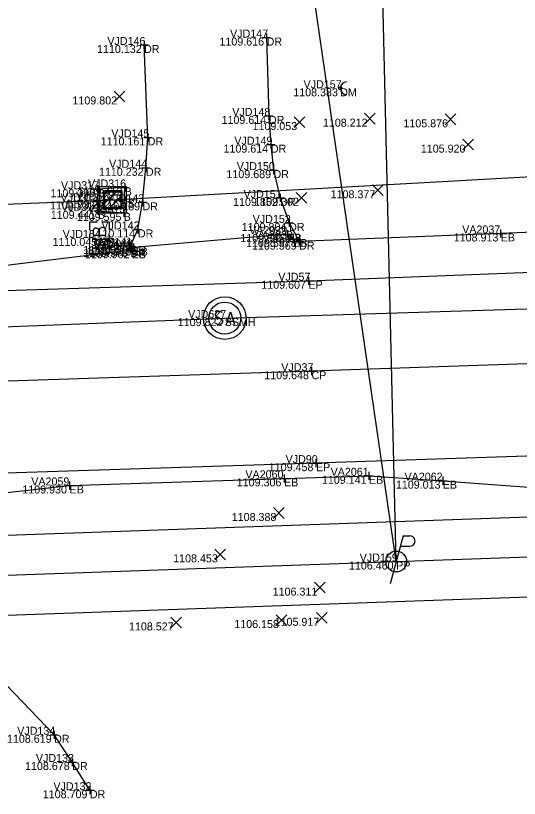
# Model space of a CAD drawing. Extents: x 1629915 to 1630675, y 484401 to 484601.
# Drawn here: x 1630022 to 1630085, y 484428.3 to 484526.1 of the extents above; entities that cross this region are included whole.
import ezdxf

# ---------------------------------------------------------------- set-up
doc = ezdxf.new("R2010")
doc.units = 0
for name, color, linetype in [('BR_X_Sub_Foot_Object', 7, 'Continuous'), ('DR_X_Cells', 7, 'Continuous'), ('DR_X_Storm_Sewer', 7, 'Continuous'), ('GK_Drainage_Nodes', 7, 'Continuous'), ('PV_X_COP', 7, 'Continuous'), ('PV_X_Driveway', 7, 'Continuous'), ('PV_X_EOP', 7, 'Continuous'), ('PV_X_Shoulder_Aggregate', 7, 'Continuous'), ('RD_X_Cells', 7, 'Continuous'), ('SV_X_Break_Lines', 7, 'Continuous'), ('SV_X_Random_Point', 7, 'Continuous'), ('SV_X_Shot_Marker', 7, 'Continuous'), ('SV_X_Text_Comment', 7, 'Continuous'), ('SV_X_Text_Elevation', 7, 'Continuous'), ('SV_X_Text_Name', 7, 'Continuous'), ('UT_X_Electric_Cells', 7, 'Continuous'), ('UT_X_Misc_Cells', 7, 'Continuous'), ('UT_X_Sanitary_Cells', 7, 'Continuous'), ('UT_X_Sanitary_Line', 7, 'Continuous')]:
    doc.layers.add(name, color=color, linetype=linetype)

msp = doc.modelspace()

# ---------------------------------------------------------------- linework, layer by layer
at = {"layer": 'BR_X_Sub_Foot_Object'}
for p, q in [((1630069.563, 484457.901), (1630057.616, 484540.101)), ((1630069.563, 484457.901), (1630067.613, 484539.935)), ((1629921.46, 484457.7), (1630334.806, 484472.223)), ((1629921.635, 484452.703), (1630334.981, 484467.226)), ((1629921.811, 484447.706), (1630335.157, 484462.229))]:
    msp.add_line(p, q, dxfattribs=at)
at = {"layer": 'DR_X_Cells'}
for p, q in [((1630032.993, 484502.475), (1630034.752, 484504.234)), ((1630032.993, 484503.607), (1630033.621, 484504.234)), ((1630033.592, 484501.943), (1630035.285, 484503.636)), ((1630034.723, 484501.943), (1630035.285, 484502.504))]:
    msp.add_line(p, q, dxfattribs=at)
for points in [[(1630032.472, 484504.755), (1630035.805, 484504.755), (1630035.805, 484501.422), (1630032.472, 484501.422)], [(1630032.993, 484504.234), (1630035.285, 484504.234), (1630035.285, 484501.943), (1630032.993, 484501.943)], [(1630033.139, 484504.088), (1630035.139, 484504.088), (1630035.139, 484502.088), (1630033.139, 484502.088)]]:
    msp.add_lwpolyline(points, close=True, dxfattribs=at)
at = {"layer": 'DR_X_Storm_Sewer'}
for p, q in [((1630034.139, 484503.088), (1630277.798, 484516.548)), ((1629929.219, 484498.911), (1630034.139, 484503.088))]:
    msp.add_line(p, q, dxfattribs=at)
at = {"layer": 'GK_Drainage_Nodes'}
for p, q in [((1630034.139, 484504.755), (1630034.139, 484504.755)), ((1630034.139, 484504.088), (1630034.139, 484504.088)), ((1630033.139, 484503.088), (1630033.139, 484503.088)), ((1630034.139, 484503.088), (1630034.139, 484503.088)), ((1630034.139, 484503.088), (1630034.139, 484503.088)), ((1630034.139, 484503.088), (1630034.139, 484503.088)), ((1630035.139, 484503.088), (1630035.139, 484503.088)), ((1630034.139, 484502.088), (1630034.139, 484502.088)), ((1630034.139, 484501.422), (1630034.139, 484501.422)), ((1630048.132, 484490.308), (1630048.132, 484490.308)), ((1630048.132, 484488.308), (1630048.132, 484488.308)), ((1630048.132, 484488.308), (1630048.132, 484488.308)), ((1630048.132, 484488.308), (1630048.132, 484488.308)), ((1630048.132, 484486.308), (1630048.132, 484486.308))]:
    msp.add_line(p, q, dxfattribs=at)
msp.add_circle((1630048.132, 484488.308), 2, dxfattribs=at)
at = {"layer": 'PV_X_COP'}
msp.add_lwpolyline([(1630268.327, 484489.246), (1630243.236, 484488.193), (1630219.614, 484487.396), (1630181.886, 484485.929), (1630141.907, 484484.591), (1630101.847, 484483.155), (1630058.972, 484481.674), (1630018.452, 484480.335), (1629978.036, 484478.791), (1629939.203, 484477.211)], dxfattribs=at)
at = {"layer": 'PV_X_Driveway'}
for points in [[(1630053.369, 484523.345), (1630053.65, 484513.559), (1630053.895, 484509.971), (1630054.225, 484506.785), (1630055.045, 484503.31), (1630056.173, 484500.192), (1630057.423, 484497.854)], [(1630036.34, 484496.941), (1630036.368, 484497.325), (1630037.277, 484499.378), (1630037.85, 484502.77), (1630038.279, 484507.079), (1630038.501, 484510.88), (1630038.044, 484522.417)], [(1630031.272, 484429.335), (1630029.073, 484432.859), (1630026.796, 484436.262), (1630014.842, 484448.677), (1630013.22, 484450.84), (1630012.363, 484454.308), (1630013.213, 484458.887), (1630014.53, 484461.746), (1630016.574, 484465.202)]]:
    msp.add_lwpolyline(points, dxfattribs=at)
at = {"layer": 'PV_X_EOP'}
for points in [[(1629938.787, 484488.624), (1629977.755, 484490.201), (1630018.109, 484491.66), (1630058.596, 484492.972), (1630101.458, 484494.639), (1630141.527, 484496.094), (1630181.4, 484497.615), (1630219.199, 484499.135), (1630242.799, 484500.003), (1630272.749, 484501.051)], [(1630263.784, 484477.407), (1630243.533, 484476.684), (1630220.003, 484475.815), (1630182.217, 484474.501), (1630142.357, 484473.071), (1630102.121, 484471.603), (1630059.531, 484470.186), (1630018.192, 484468.838), (1629978.308, 484467.435), (1629939.56, 484465.905)]]:
    msp.add_lwpolyline(points, dxfattribs=at)
at = {"layer": 'PV_X_Shoulder_Aggregate'}
for points in [[(1630275.858, 484507.82), (1630275.935, 484508.43), (1630251.773, 484507.981), (1630226.056, 484507.184), (1630204.993, 484506.289), (1630180.178, 484504.732), (1630155.752, 484502.786), (1630130.505, 484501.377), (1630107.341, 484499.869), (1630082.614, 484498.877), (1630057.423, 484497.854), (1630056.684, 484498.178), (1630055.974, 484498.791), (1630036.737, 484497.117), (1630036.516, 484496.78), (1630005.439, 484492.996), (1629981.146, 484491.329), (1629968.094, 484490.842), (1629967.166, 484490.748), (1629965.306, 484491.801), (1629947.85, 484491.524), (1629935.773, 484490.2), (1629921.037, 484489.433)], [(1629924.92, 484463.104), (1629930.051, 484463.83), (1629958.351, 484464.985), (1629985.484, 484465.939), (1629989.882, 484465.788), (1629994.282, 484464.53), (1629995.636, 484464.345), (1630011.361, 484464.736), (1630016.574, 484465.202), (1630018.985, 484466.333), (1630028.743, 484467.401), (1630055.537, 484468.29), (1630066.153, 484468.607), (1630075.383, 484468), (1630095.195, 484466.534), (1630119.644, 484467.176), (1630148.034, 484467.946), (1630167.26, 484468.813), (1630191.18, 484469.683), (1630216.422, 484470.188), (1630228.431, 484470.017), (1630254.625, 484470.782), (1630261.494, 484471.006)]]:
    msp.add_lwpolyline(points, dxfattribs=at)
at = {"layer": 'RD_X_Cells'}
for p, q in [((1630031.261, 484497.807), (1630031.261, 484498.808)), ((1630033.704, 484497.807), (1630033.704, 484498.808)), ((1630032.482, 484498.318), (1630032.482, 484498.318))]:
    msp.add_line(p, q, dxfattribs=at)
for points in [[(1630031.261, 484499.325), (1630031.261, 484500.318), (1630032.231, 484500.318)], [(1630032.734, 484500.318), (1630033.704, 484500.318), (1630033.704, 484499.325)], [(1630032.413, 484499.34), (1630032.35, 484499.403), (1630032.312, 484499.441), (1630032.275, 484499.466), (1630032.249, 484499.479), (1630032.199, 484499.504), (1630032.161, 484499.516), (1630032.073, 484499.542), (1630032.035, 484499.542), (1630031.985, 484499.542), (1630031.909, 484499.529), (1630031.846, 484499.504), (1630031.796, 484499.466), (1630031.745, 484499.403), (1630031.72, 484499.353), (1630031.708, 484499.327), (1630031.682, 484499.264), (1630031.682, 484498.647), (1630033.282, 484498.647), (1630033.282, 484499.34), (1630033.232, 484499.428), (1630033.169, 484499.504), (1630033.068, 484499.567), (1630032.955, 484499.605), (1630032.841, 484499.617), (1630032.766, 484499.617), (1630032.69, 484499.592), (1630032.577, 484499.542), (1630032.501, 484499.479), (1630032.413, 484499.34), (1630032.413, 484498.647)], [(1630033.282, 484497.022), (1630031.682, 484497.022), (1630033.282, 484497.601), (1630031.682, 484498.156), (1630033.282, 484498.156)], [(1630032.231, 484496.318), (1630031.261, 484496.318), (1630031.261, 484497.288)], [(1630033.704, 484497.288), (1630033.704, 484496.318), (1630032.734, 484496.318)]]:
    msp.add_lwpolyline(points, dxfattribs=at)
at = {"layer": 'SV_X_Break_Lines'}
msp.add_lwpolyline([(1630032.155, 484502.881), (1630032.273, 484501.704), (1630035.509, 484501.451), (1630035.629, 484504.618), (1630032.237, 484504.402)], dxfattribs=at)
at = {"layer": 'SV_X_Random_Point'}
for p, q in [((1630034.301, 484515.325), (1630035.635, 484516.66)), ((1630034.301, 484516.66), (1630035.635, 484515.325)), ((1630056.798, 484512.124), (1630058.131, 484513.459)), ((1630056.798, 484513.459), (1630058.131, 484512.124)), ((1630065.604, 484512.549), (1630066.937, 484513.884)), ((1630065.604, 484513.884), (1630066.937, 484512.549)), ((1630075.695, 484512.465), (1630077.029, 484513.8)), ((1630075.695, 484513.8), (1630077.029, 484512.465)), ((1630077.883, 484509.31), (1630079.216, 484510.645)), ((1630077.883, 484510.645), (1630079.216, 484509.31)), ((1630066.591, 484503.602), (1630067.925, 484504.937)), ((1630066.591, 484504.937), (1630067.925, 484503.602)), ((1630057.038, 484502.676), (1630058.372, 484504.011)), ((1630057.038, 484504.011), (1630058.372, 484502.676)), ((1630054.24, 484463.294), (1630055.573, 484464.629)), ((1630054.24, 484464.629), (1630055.573, 484463.294)), ((1630046.88, 484458.128), (1630048.213, 484459.463)), ((1630046.88, 484459.463), (1630048.213, 484458.128)), ((1630059.336, 484453.971), (1630060.669, 484455.306)), ((1630059.336, 484455.306), (1630060.669, 484453.971)), ((1630041.392, 484449.626), (1630042.725, 484450.961)), ((1630041.392, 484450.961), (1630042.725, 484449.626)), ((1630054.555, 484449.922), (1630055.888, 484451.257)), ((1630054.555, 484451.257), (1630055.888, 484449.922)), ((1630059.594, 484450.204), (1630060.927, 484451.539)), ((1630059.594, 484451.539), (1630060.927, 484450.204))]:
    msp.add_line(p, q, dxfattribs=at)
at = {"layer": 'SV_X_Shot_Marker'}
for p, q in [((1630052.869, 484523.345), (1630053.869, 484523.345)), ((1630053.369, 484523.845), (1630053.369, 484522.845)), ((1630053.369, 484523.345), (1630053.369, 484523.345)), ((1630037.544, 484522.417), (1630038.544, 484522.417)), ((1630038.044, 484522.917), (1630038.044, 484521.917)), ((1630038.044, 484522.417), (1630038.044, 484522.417)), ((1630053.15, 484513.559), (1630054.15, 484513.559)), ((1630053.65, 484514.059), (1630053.65, 484513.059)), ((1630053.65, 484513.559), (1630053.65, 484513.559)), ((1630038.001, 484510.88), (1630039.001, 484510.88)), ((1630038.501, 484511.38), (1630038.501, 484510.38)), ((1630038.501, 484510.88), (1630038.501, 484510.88)), ((1630053.895, 484510.471), (1630053.895, 484509.471)), ((1630053.395, 484509.971), (1630054.395, 484509.971)), ((1630053.895, 484509.971), (1630053.895, 484509.971)), ((1630038.279, 484507.579), (1630038.279, 484506.579)), ((1630037.779, 484507.079), (1630038.779, 484507.079)), ((1630038.279, 484507.079), (1630038.279, 484507.079)), ((1630053.725, 484506.785), (1630054.725, 484506.785)), ((1630054.225, 484507.285), (1630054.225, 484506.285)), ((1630054.225, 484506.785), (1630054.225, 484506.785)), ((1630032.237, 484504.902), (1630032.237, 484503.902)), ((1630035.129, 484504.618), (1630036.129, 484504.618)), ((1630035.629, 484505.118), (1630035.629, 484504.118)), ((1630035.629, 484504.618), (1630035.629, 484504.618)), ((1630031.737, 484504.402), (1630032.737, 484504.402)), ((1630032.237, 484504.402), (1630032.237, 484504.402)), ((1630055.045, 484503.81), (1630055.045, 484502.81)), ((1630031.655, 484502.881), (1630032.655, 484502.881)), ((1630032.155, 484503.381), (1630032.155, 484502.381)), ((1630032.155, 484502.881), (1630032.155, 484502.881)), ((1630037.35, 484502.77), (1630038.35, 484502.77)), ((1630037.85, 484503.27), (1630037.85, 484502.27)), ((1630037.85, 484502.77), (1630037.85, 484502.77)), ((1630054.545, 484503.31), (1630055.545, 484503.31)), ((1630055.045, 484503.31), (1630055.045, 484503.31)), ((1630031.773, 484501.704), (1630032.773, 484501.704)), ((1630032.273, 484502.204), (1630032.273, 484501.204)), ((1630032.273, 484501.704), (1630032.273, 484501.704)), ((1630035.509, 484501.951), (1630035.509, 484500.951)), ((1630035.009, 484501.451), (1630036.009, 484501.451)), ((1630035.509, 484501.451), (1630035.509, 484501.451)), ((1630056.173, 484500.692), (1630056.173, 484499.692)), ((1630037.277, 484499.878), (1630037.277, 484498.878)), ((1630055.673, 484500.192), (1630056.673, 484500.192)), ((1630056.173, 484500.192), (1630056.173, 484500.192)), ((1630036.777, 484499.378), (1630037.777, 484499.378)), ((1630037.277, 484499.378), (1630037.277, 484499.378)), ((1630055.474, 484498.791), (1630056.474, 484498.791)), ((1630055.974, 484499.291), (1630055.974, 484498.291)), ((1630055.974, 484498.791), (1630055.974, 484498.791)), ((1630082.114, 484498.877), (1630083.114, 484498.877)), ((1630082.614, 484499.377), (1630082.614, 484498.377)), ((1630082.614, 484498.877), (1630082.614, 484498.877)), ((1630036.368, 484497.825), (1630036.368, 484496.825)), ((1630056.184, 484498.178), (1630057.184, 484498.178)), ((1630056.684, 484498.678), (1630056.684, 484497.678)), ((1630056.684, 484498.178), (1630056.684, 484498.178)), ((1630056.923, 484497.854), (1630057.923, 484497.854)), ((1630057.423, 484498.354), (1630057.423, 484497.354)), ((1630057.423, 484497.854), (1630057.423, 484497.854)), ((1630035.84, 484496.941), (1630036.84, 484496.941)), ((1630035.868, 484497.325), (1630036.868, 484497.325)), ((1630036.016, 484496.78), (1630037.016, 484496.78)), ((1630036.237, 484497.117), (1630037.237, 484497.117)), ((1630036.34, 484497.441), (1630036.34, 484496.441)), ((1630036.34, 484496.941), (1630036.34, 484496.941)), ((1630036.368, 484497.325), (1630036.368, 484497.325)), ((1630036.516, 484497.28), (1630036.516, 484496.28)), ((1630036.516, 484496.78), (1630036.516, 484496.78)), ((1630036.737, 484497.617), (1630036.737, 484496.617)), ((1630036.737, 484497.117), (1630036.737, 484497.117)), ((1630058.096, 484492.972), (1630059.096, 484492.972)), ((1630058.596, 484493.472), (1630058.596, 484492.472)), ((1630058.596, 484492.972), (1630058.596, 484492.972)), ((1630058.972, 484482.174), (1630058.972, 484481.174)), ((1630058.472, 484481.674), (1630059.472, 484481.674)), ((1630058.972, 484481.674), (1630058.972, 484481.674)), ((1630059.531, 484470.686), (1630059.531, 484469.686)), ((1630059.031, 484470.186), (1630060.031, 484470.186)), ((1630059.531, 484470.186), (1630059.531, 484470.186)), ((1630055.537, 484468.79), (1630055.537, 484467.79)), ((1630065.653, 484468.607), (1630066.653, 484468.607)), ((1630066.153, 484469.107), (1630066.153, 484468.107)), ((1630066.153, 484468.607), (1630066.153, 484468.607)), ((1630075.383, 484468.5), (1630075.383, 484467.5)), ((1630028.243, 484467.401), (1630029.243, 484467.401)), ((1630028.743, 484467.901), (1630028.743, 484466.901)), ((1630028.743, 484467.401), (1630028.743, 484467.401)), ((1630055.037, 484468.29), (1630056.037, 484468.29)), ((1630055.537, 484468.29), (1630055.537, 484468.29)), ((1630074.883, 484468), (1630075.883, 484468)), ((1630075.383, 484468), (1630075.383, 484468)), ((1630026.296, 484436.262), (1630027.296, 484436.262)), ((1630026.796, 484436.762), (1630026.796, 484435.762)), ((1630026.796, 484436.262), (1630026.796, 484436.262)), ((1630029.073, 484433.359), (1630029.073, 484432.359)), ((1630028.573, 484432.859), (1630029.573, 484432.859)), ((1630029.073, 484432.859), (1630029.073, 484432.859)), ((1630030.772, 484429.335), (1630031.772, 484429.335)), ((1630031.272, 484429.835), (1630031.272, 484428.835)), ((1630031.272, 484429.335), (1630031.272, 484429.335))]:
    msp.add_line(p, q, dxfattribs=at)
at = {"layer": 'UT_X_Electric_Cells'}
for p, q in [((1630070.419, 484461.101), (1630068.813, 484455.101)), ((1630070.419, 484461.101), (1630071.269, 484461.101)), ((1630070.078, 484459.826), (1630071.269, 484459.826))]:
    msp.add_line(p, q, dxfattribs=at)
msp.add_circle((1630069.563, 484457.901), 1.3, dxfattribs=at)
msp.add_arc((1630071.282, 484460.463), 0.638, 268.8767, 91.1233, dxfattribs=at)
at = {"layer": 'UT_X_Misc_Cells'}
msp.add_circle((1630062.557, 484517.01), 0.2, dxfattribs=at)
msp.add_arc((1630063.357, 484517.01), 0.8, 90, 270, dxfattribs=at)
at = {"layer": 'UT_X_Sanitary_Cells'}
for points in [[(1630047.799, 484488.995), (1630047.774, 484489.02), (1630047.736, 484489.045), (1630047.623, 484489.083), (1630047.484, 484489.108), (1630047.383, 484489.108), (1630047.346, 484489.108), (1630047.182, 484489.07), (1630047.043, 484488.995), (1630046.955, 484488.894), (1630046.93, 484488.793), (1630046.93, 484488.718), (1630046.955, 484488.617), (1630047.056, 484488.529), (1630047.749, 484488.151), (1630047.812, 484488.1), (1630047.837, 484488.05), (1630047.862, 484487.974), (1630047.862, 484487.899), (1630047.85, 484487.823), (1630047.837, 484487.773), (1630047.812, 484487.71), (1630047.787, 484487.659), (1630047.761, 484487.622), (1630047.724, 484487.584), (1630047.686, 484487.559), (1630047.635, 484487.533), (1630047.598, 484487.521), (1630047.484, 484487.508), (1630047.308, 484487.508), (1630047.195, 484487.533), (1630047.031, 484487.622), (1630046.93, 484487.697)], [(1630048.341, 484487.508), (1630048.845, 484489.108), (1630049.336, 484487.508)], [(1630049.21, 484487.886), (1630048.467, 484487.886)]]:
    msp.add_lwpolyline(points, dxfattribs=at)
for radius in [2.667, 2]:
    msp.add_circle((1630048.132, 484488.308), radius, dxfattribs=at)
at = {"layer": 'UT_X_Sanitary_Line'}
msp.add_lwpolyline([(1629930.746, 484483.734), (1630048.132, 484488.308), (1630252.717, 484494.605), (1630261.76, 484567.793), (1630373.422, 484500.095), (1630654.857, 484509.349)], dxfattribs=at)

# ---------------------------------------------------------------- texts
at = {"layer": 'SV_X_Text_Comment'}
for s, p in [('DR', (1630053.369, 484522.345)), ('DR', (1630038.044, 484521.417)), ('DM', (1630062.557, 484516.01)), ('DR', (1630053.65, 484512.559)), ('DR', (1630038.501, 484509.88)), ('DR', (1630053.895, 484508.971)), ('DR', (1630038.279, 484506.079)), ('DR', (1630054.225, 484505.785)), ('B', (1630035.629, 484503.618)), ('B', (1630032.237, 484503.402)), ('B', (1630032.155, 484501.881)), ('CBS', (1630034.139, 484502.088)), ('DR', (1630037.85, 484501.77)), ('DR', (1630055.045, 484502.31)), ('B', (1630032.273, 484500.704)), ('B', (1630035.509, 484500.451)), ('DR', (1630056.173, 484499.192)), ('DR', (1630037.277, 484498.378)), ('EB', (1630055.974, 484497.791)), ('EB', (1630082.614, 484497.877)), ('MB', (1630032.482, 484497.318)), ('EB', (1630056.684, 484497.178)), ('DR', (1630057.423, 484496.854)), ('DR', (1630036.34, 484495.941)), ('DR', (1630036.368, 484496.325)), ('EB', (1630036.516, 484495.78)), ('EB', (1630036.737, 484496.117)), ('EP', (1630058.596, 484491.972)), ('SSMH', (1630048.132, 484487.308)), ('CP', (1630058.972, 484480.674)), ('EP', (1630059.531, 484469.186)), ('EB', (1630066.153, 484467.607)), ('EB', (1630028.743, 484466.401)), ('EB', (1630055.537, 484467.29)), ('EB', (1630075.383, 484467)), ('PP', (1630069.563, 484456.901)), ('DR', (1630026.796, 484435.262)), ('DR', (1630029.073, 484431.859)), ('DR', (1630031.272, 484428.335))]:
    msp.add_text(s, height=1, dxfattribs=at).set_placement(p)
at = {"layer": 'SV_X_Text_Elevation'}
for s, p in [('1109.616', (1630047.467, 484522.345)), ('1110.132', (1630032.172, 484521.417)), ('1108.383', (1630056.695, 484516.01)), ('1109.802', (1630029.097, 484514.992)), ('1109.614', (1630047.73, 484512.559)), ('1109.053', (1630051.603, 484511.792)), ('1108.212', (1630060.399, 484512.217)), ('1105.876', (1630070.46, 484512.133)), ('1110.161', (1630032.621, 484509.88)), ('1109.614', (1630047.975, 484508.971)), ('1105.920', (1630072.638, 484508.978)), ('1110.232', (1630032.407, 484506.079)), ('1109.689', (1630048.343, 484505.785)), ('1109.412', (1630029.758, 484503.618)), ('1109.399', (1630026.356, 484503.402)), ('1108.377', (1630061.364, 484503.27)), ('1109.232', (1630026.284, 484501.881)), ('1109.262', (1630028.267, 484502.088)), ('1110.189', (1630031.968, 484501.77)), ('1109.852', (1630049.174, 484502.31)), ('1109.302', (1630051.834, 484502.343)), ('1109.441', (1630026.394, 484500.704)), ('1109.595', (1630029.641, 484500.451)), ('1109.804', (1630050.252, 484499.192)), ('1110.114', (1630031.356, 484498.378)), ('1109.586', (1630050.072, 484497.791)), ('1108.913', (1630076.752, 484497.877)), ('1110.045', (1630026.614, 484497.318)), ('1109.597', (1630050.79, 484497.178)), ('1109.569', (1630051.541, 484496.854)), ('1109.976', (1630030.438, 484495.941)), ('1110.030', (1630030.457, 484496.325)), ('1109.962', (1630030.645, 484495.78)), ('1109.915', (1630030.868, 484496.117)), ('1109.607', (1630052.702, 484491.972)), ('1109.822', (1630042.26, 484487.308)), ('1109.648', (1630053.074, 484480.674)), ('1109.458', (1630053.633, 484469.186)), ('1109.141', (1630060.273, 484467.607)), ('1109.930', (1630022.831, 484466.401)), ('1109.306', (1630049.635, 484467.29)), ('1109.013', (1630069.521, 484467)), ('1108.388', (1630049.008, 484462.962)), ('1108.453', (1630041.685, 484457.796)), ('1106.460', (1630063.651, 484456.901)), ('1106.311', (1630054.123, 484453.639)), ('1105.917', (1630054.367, 484449.871)), ('1108.527', (1630036.165, 484449.294)), ('1106.158', (1630049.323, 484449.59)), ('1108.619', (1630020.915, 484435.262)), ('1108.678', (1630023.174, 484431.859)), ('1108.709', (1630025.39, 484428.335))]:
    msp.add_text(s, height=1, dxfattribs=at).set_placement(p)
at = {"layer": 'SV_X_Text_Name'}
for s, p in [('VJD147', (1630048.793, 484523.345)), ('VJD146', (1630033.46, 484522.417)), ('VJD157', (1630057.981, 484517.01)), ('VJD148', (1630049.07, 484513.559)), ('VJD145', (1630033.95, 484510.88)), ('VJD149', (1630049.332, 484509.971)), ('VJD144', (1630033.677, 484507.079)), ('VJD150', (1630049.632, 484506.785)), ('VJD316', (1630031.045, 484504.618)), ('VJD317', (1630027.662, 484504.402)), ('VJD313', (1630027.612, 484502.881)), ('VJD628', (1630029.559, 484503.088)), ('VJD143', (1630033.306, 484502.77)), ('VJD151', (1630050.484, 484503.31)), ('VJD314', (1630027.672, 484501.704)), ('VJD315', (1630030.959, 484501.451)), ('VJD152', (1630051.62, 484500.192)), ('VJD142', (1630032.723, 484499.378)), ('VA2039', (1630051.18, 484498.791)), ('VA2037', (1630077.807, 484498.877)), ('VJD154', (1630027.881, 484498.318)), ('VA2038', (1630051.873, 484498.178)), ('VJD153', (1630052.879, 484497.854)), ('VA2041', (1630031.724, 484496.78)), ('VJD140', (1630031.747, 484496.941)), ('VJD141', (1630031.807, 484497.325)), ('VA2040', (1630031.913, 484497.117)), ('VJD57', (1630054.819, 484492.972)), ('VJD627', (1630043.556, 484488.308)), ('VJD37', (1630055.195, 484481.674)), ('VJD90', (1630055.736, 484470.186)), ('VA2061', (1630061.361, 484468.607)), ('VA2059', (1630023.949, 484467.401)), ('VA2060', (1630050.713, 484468.29)), ('VA2062', (1630070.599, 484468)), ('VJD159', (1630064.999, 484457.901)), ('VJD134', (1630022.194, 484436.262)), ('VJD133', (1630024.529, 484432.859)), ('VJD132', (1630026.719, 484429.335))]:
    msp.add_text(s, height=1, dxfattribs=at).set_placement(p)

doc.saveas('drawing.dxf')
